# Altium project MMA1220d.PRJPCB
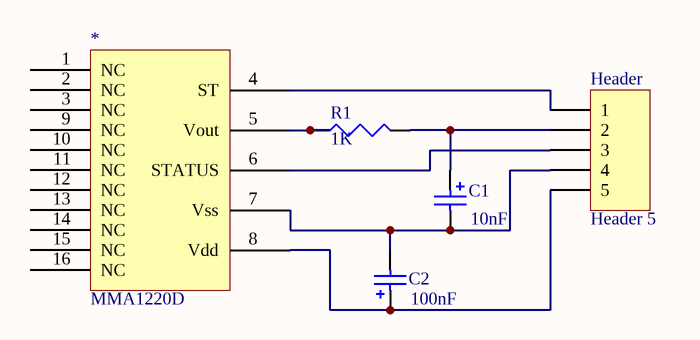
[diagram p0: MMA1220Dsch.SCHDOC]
1 sheet, 5 parts. Net scope: global (net labels, ports and power ports of the same name join across sheets).
Board file: MMA1220dprj.PCBDOC

## Sheet MMA1220Dsch.SCHDOC
size A4

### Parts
C1  value 10nF  [CC2012-0805]  (hidden comment: Cap Pol3)
C2  value 100nF  [CC2012-0805]  (hidden comment: Cap Pol3)
Header  Header 5  [HDR1X5]
MMA1220D  MMA1220D  [SO-G16/D10.3]
R1  value 1K  [C1608-0603]  (hidden comment: Res3)

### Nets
NetC1_1: C1.1 Header.2 R1.2
NetC1_2: C1.2 C2.2 Header.4 MMA1220D.7(Vss)
NetC2_1: C2.1 Header.5 MMA1220D.8(Vdd)
NetHeader_1: Header.1 MMA1220D.4(ST)
NetHeader_3: Header.3 MMA1220D.6(STATUS)
NetMMA1220D_5: MMA1220D.5(Vout) R1.1

Not connected (* = marked no-connect by the designer): MMA1220D 1(NC) 2(NC) 3(NC) 9(NC) 10(NC) 11(NC) 12(NC) 13(NC) 14(NC) 15(NC) 16(NC)

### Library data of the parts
C1 C2 = Cap Pol3: Polarized Capacitor (Surface Mount)
Header = Header 5: Header, 5-Pin
R1 = Res3: Resistor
